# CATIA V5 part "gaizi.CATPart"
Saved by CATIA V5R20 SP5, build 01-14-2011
Part number: 555
Bounding box of the stored display mesh (mm): x -170.559 to 178.441, y -223.438 to 26.562, z 0 to 40
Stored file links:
  C:\Documents and Settings\Student\桌面\zuoping\gaizi.CATPart
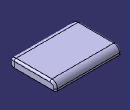
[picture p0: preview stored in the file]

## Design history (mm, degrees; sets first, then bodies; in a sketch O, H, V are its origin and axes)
Body1 (main body)
  Sketch1 on xy-plane, origin (0, 0, 0), H (1, 0, 0), V (0, 1, 0)
    line L1 (-170.5594, 26.5619) -> (178.4406, 26.5619)
    line L2 (178.4406, 26.5619) -> (178.4406, -223.4381)
    line L3 (178.4406, -223.4381) -> (-170.5594, -223.4381)
    line L4 (-170.5594, -223.4381) -> (-170.5594, 26.5619)
    length L1 = 349
    length L2 = 250
    horizontal: L1 H, L3 H
    vertical: L2 V, L4 V
  Pad1: profile Sketch1, direction (0, 0, 1), length 40
  Sketch2 on face of Pad1 from Sketch1.L4, origin (-170.5594, 0, 0), H (0, -1, 0), V (0, 0, 1)
    circle A1 centre (-6.6552, 15) radius 10
    point P1 (-6.6552, 15)
    reference projected line E1 (-26.5619, 0) -> (223.4381, 0) from edge [start face of Pad1 | face of Pad1 from Sketch1.L4]
    radius A1 = 10
    distance P1 E1 = 15
  Pocket1: profile Sketch2, direction (1, 0, 0), length 50
  Fillet1: radius 30, on edge [face of Pad1 from Sketch1.L1 | end face of Pad1]
  Fillet2: radius 10, on edge [face of Pad1 from Sketch1.L4 | end face of Pad1]
  Fillet3: radius 10, on edge [face of Pad1 from Sketch1.L2 | end face of Pad1]
  Fillet4: radius 30, on edge [face of Pad1 from Sketch1.L3 | end face of Pad1]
